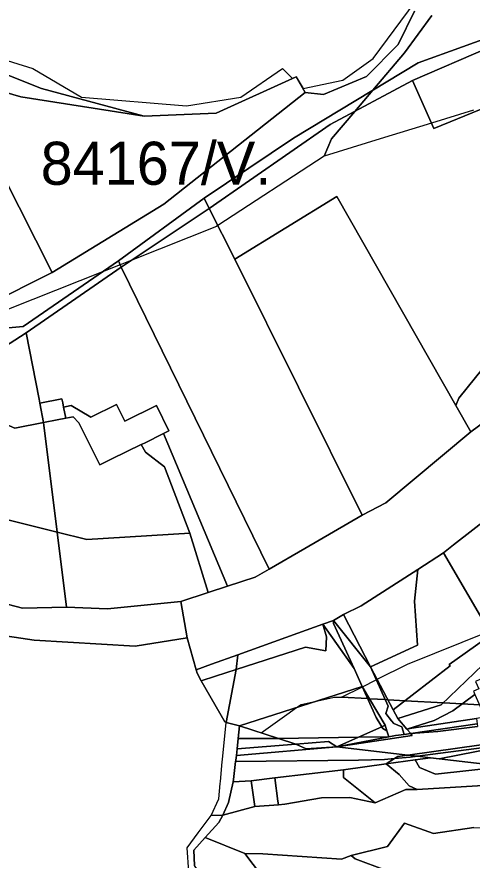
# Model space of a CAD drawing. Extents: x -477304 to -465429, y -1159113 to -1149210.
# Drawn here: x -476165.5 to -476007, y -1154887.3 to -1154593.5 of the extents above; entities that cross this region are included whole.
import ezdxf

# ---------------------------------------------------------------- set-up
doc = ezdxf.new("R2010")
doc.units = 0
for name, color, linetype in [('BPEJ_s', 7, 'Continuous'), ('ostatni_s', 7, 'Continuous'), ('PUPFL_s', 7, 'Continuous'), ('trav_porost_s', 7, 'Continuous'), ('voda_s', 7, 'Continuous'), ('zahrada_s', 7, 'Continuous')]:
    doc.layers.add(name, color=color, linetype=linetype)

msp = doc.modelspace()

# ---------------------------------------------------------------- linework, layer by layer
at = {"layer": 'BPEJ_s'}
msp.add_line((-476052.5, -1154830.5), (-476045.2, -1154826.85), dxfattribs=at)
for points in [[(-476198.5, -1154599.5), (-476160, -1154611.5), (-476143, -1154621.5), (-476106.5, -1154624.5), (-476087.5, -1154621.5), (-476073, -1154611.5), (-476069.54, -1154614.96), (-476068.28, -1154614.39), (-476065.87, -1154618.47), (-476052, -1154615.5), (-476041.5, -1154608), (-476014.5, -1154571.5)], [(-476198.5, -1154599.5), (-476160, -1154611.5), (-476143, -1154621.5), (-476106.5, -1154624.5), (-476087.5, -1154621.5), (-476073, -1154611.5), (-476069.54, -1154614.96), (-476068.28, -1154614.39), (-476065.87, -1154618.47), (-476052, -1154615.5), (-476041.5, -1154608), (-476014.5, -1154571.5)], [(-476021.05, -1154592.95), (-476030.5, -1154606), (-476041.52, -1154618.96), (-476047.84, -1154626.4), (-476056, -1154636), (-476058.5, -1154641.98), (-476095.53, -1154666.19), (-476096, -1154666.5), (-476125.52, -1154678.23), (-476129.54, -1154679.83), (-476135.67, -1154682.27), (-476176.5, -1154698.5)], [(-476006.5, -1154626), (-476021.15, -1154630.51), (-476039, -1154636), (-476058.5, -1154641.98), (-476056, -1154636), (-476047.84, -1154626.4), (-476041.52, -1154618.96), (-476030.5, -1154606), (-476021.05, -1154592.95)], [(-476006.5, -1154626), (-476021.15, -1154630.51), (-476039, -1154636), (-476058.5, -1154641.98), (-476095.53, -1154666.19), (-476096, -1154666.5), (-476125.52, -1154678.23), (-476129.54, -1154679.83), (-476135.67, -1154682.27), (-476176.5, -1154698.5)], [(-476186.81, -1154806.62), (-476159.5, -1154810.64), (-476124.34, -1154812.7), (-476106.2, -1154809.85), (-476103.13, -1154820.94), (-476102.8, -1154822.12), (-476101.3, -1154824.75), (-476093.12, -1154839.08), (-476092.69, -1154839.28), (-476087.95, -1154840.53), (-476080.5, -1154842.93), (-476071.5, -1154836.5), (-476068.12, -1154834.14), (-476066.5, -1154833), (-476060.67, -1154831.73), (-476055, -1154830.5), (-476052.5, -1154830.5)], [(-476004.4, -1154833.17), (-476010.4, -1154832.84), (-476017.01, -1154832.47), (-476030.35, -1154831.73), (-476036.27, -1154831.4), (-476037.28, -1154831.35), (-476039.94, -1154831.2), (-476042.7, -1154831.04), (-476043.32, -1154831.01), (-476052.5, -1154830.5), (-476045.2, -1154826.85), (-476040.36, -1154824.43), (-476040.05, -1154824.28), (-476029.5, -1154819), (-476000.96, -1154807.55)], [(-476045.2, -1154826.85), (-476040.36, -1154824.43), (-476040.05, -1154824.28), (-476029.5, -1154819), (-476000.96, -1154807.55)], [(-476105.62, -1154891.31), (-476106.27, -1154882.94), (-476102.42, -1154877.81), (-476101.31, -1154876.33), (-476097.86, -1154871.73), (-476095.23, -1154865.95), (-476094.73, -1154860.63), (-476094.65, -1154859.83), (-476094, -1154853.04), (-476093.92, -1154852.23), (-476092.69, -1154839.28), (-476087.95, -1154840.53), (-476080.5, -1154842.93), (-476071.5, -1154836.5), (-476068.12, -1154834.14), (-476066.5, -1154833), (-476060.67, -1154831.73), (-476055, -1154830.5), (-476052.5, -1154830.5), (-476043.32, -1154831.01), (-476042.7, -1154831.04), (-476039.94, -1154831.2), (-476037.28, -1154831.35), (-476036.27, -1154831.4), (-476030.35, -1154831.73), (-476017.01, -1154832.47), (-476010.4, -1154832.84), (-476004.4, -1154833.17)]]:
    msp.add_lwpolyline(points, dxfattribs=at)
at = {"layer": 'ostatni_s'}
for points in [[(-475922.61, -1154664.03), (-475947.5, -1154680.92), (-475971.18, -1154711.25), (-476007.43, -1154738.07), (-476012.67, -1154728.85), (-476011.62, -1154726.29), (-475984.03, -1154692.11), (-475951.02, -1154670.96), (-475939.87, -1154667.27), (-475936.86, -1154666.04), (-475923.5, -1154662.02)], [(-476196.33, -1154719.12), (-476196.8, -1154718.13), (-476175.59, -1154708.18), (-476177.93, -1154703.42), (-476176.24, -1154702.49), (-476163.4, -1154701.34), (-476130.13, -1154678.46), (-476129.17, -1154680.68), (-476162.29, -1154703.52), (-476171.9, -1154709.68), (-476172.72, -1154707.98)], [(-476175.38, -1154732.86), (-476180.53, -1154730.65), (-476187.48, -1154730.16), (-476169.24, -1154721.57), (-476168.8, -1154721.36), (-476169.61, -1154719.63), (-476173.24, -1154711.89), (-476171.28, -1154710.96), (-476171.9, -1154709.68), (-476162.29, -1154703.52), (-476157.81, -1154726.68), (-476157.54, -1154728.08), (-476156.24, -1154734.8), (-476166.3, -1154736.74)], [(-476156.24, -1154734.8), (-476157.54, -1154728.08), (-476149.85, -1154726.59), (-476149.59, -1154727.93), (-476149.31, -1154729.41), (-476148.55, -1154733.32), (-476151.52, -1154733.89)], [(-476146.68, -1154728.9), (-476139.75, -1154732.91), (-476130.84, -1154728.5), (-476127.94, -1154734.35), (-476116.97, -1154728.9), (-476112.59, -1154737.73), (-476114.43, -1154738.65), (-476121.15, -1154741.97), (-476122.22, -1154742.49), (-476132.51, -1154747.51), (-476136.67, -1154749.57), (-476143.91, -1154734.97), (-476145.93, -1154732.81), (-476148.55, -1154733.32), (-476149.31, -1154729.41)], [(-476174.99, -1154749.93), (-476175.08, -1154744.99), (-476186.99, -1154745.21), (-476182.21, -1154733.26), (-476175.38, -1154732.86), (-476166.3, -1154736.74), (-476156.24, -1154734.8), (-476151.49, -1154773.02), (-476197.51, -1154761.46), (-476191.03, -1154754.54), (-476189.15, -1154750.19)], [(-476114.43, -1154738.65), (-476092.16, -1154791.84), (-476098.93, -1154794.07), (-476105.33, -1154773.37), (-476114.16, -1154750.21), (-476120.78, -1154745.13), (-476122.22, -1154742.49), (-476121.15, -1154741.97)], [(-475972.08, -1154779.37), (-475973.8, -1154781.4), (-475992.24, -1154798.8), (-476000.81, -1154807.81), (-476016.97, -1154780.18), (-476013.49, -1154777.42), (-475988.63, -1154758.17)], [(-476034.43, -1154834.87), (-476042.39, -1154819.88), (-476026, -1154812.35), (-476027.08, -1154796.99), (-476025.92, -1154785.97), (-476016.97, -1154780.18), (-476000.81, -1154807.81), (-476003.08, -1154810.63), (-476015.02, -1154819.11), (-476014.63, -1154819.62)], [(-476051.8, -1154801.71), (-476042.39, -1154819.88), (-476055.27, -1154803.77)], [(-476065.05, -1154813.06), (-476089.16, -1154820.83), (-476088.63, -1154815.71), (-476067.68, -1154808.25), (-476058.96, -1154805.1), (-476057.66, -1154809.45), (-476057.88, -1154814.34)], [(-476055.29, -1154804.78), (-476048.12, -1154820.49), (-476058.96, -1154805.1), (-476055.27, -1154803.77)], [(-476037.07, -1154836.18), (-476035.01, -1154838.74), (-476034.3, -1154839.62), (-476031.49, -1154840.79), (-476030.7, -1154843.48), (-476033.65, -1154843.9), (-476035.96, -1154844.3), (-476036.75, -1154842.19), (-476037.23, -1154840.25), (-476045.25, -1154826.76), (-476048.12, -1154820.49), (-476055.29, -1154804.78), (-476055.27, -1154803.77), (-476042.39, -1154819.88), (-476036.27, -1154833.6)], [(-476103.13, -1154820.94), (-476097.75, -1154819), (-476088.63, -1154815.71), (-476089.16, -1154820.83), (-476096.32, -1154823.14), (-476101.3, -1154824.75), (-476102.8, -1154822.12)], [(-476093.12, -1154839.08), (-476101.3, -1154824.75), (-476096.32, -1154823.14), (-476089.16, -1154820.83), (-476092.69, -1154839.28)], [(-476036.27, -1154833.6), (-476042.39, -1154819.88), (-476034.43, -1154834.87), (-476032.81, -1154837.91), (-476029.68, -1154841.62), (-476028.39, -1154843.15), (-476030.7, -1154843.48), (-476031.49, -1154840.79), (-476034.3, -1154839.62), (-476035.01, -1154838.74), (-476037.07, -1154836.18)], [(-476045.25, -1154826.76), (-476037.23, -1154840.25), (-476038.46, -1154840.8), (-476038.76, -1154840.3), (-476040.36, -1154837.54)], [(-476028.39, -1154843.15), (-476029.68, -1154841.62), (-476028.03, -1154841.35), (-476005.51, -1154837.95), (-476005.26, -1154839.83)], [(-476074.46, -1154844.88), (-476088.45, -1154844.95), (-476087.95, -1154840.53)], [(-476038.46, -1154840.8), (-476037.23, -1154840.25), (-476036.75, -1154842.19), (-476038.09, -1154841.44)], [(-476028.39, -1154843.15), (-476005.26, -1154839.83), (-476005.14, -1154840.75), (-476018.94, -1154842.48)], [(-476074.46, -1154844.88), (-476046.61, -1154844.46), (-476054.11, -1154847.83), (-476057.03, -1154845.94), (-476068.39, -1154846.84)], [(-476027.82, -1154843.83), (-476054.11, -1154847.83), (-476035.96, -1154844.3), (-476033.65, -1154843.9), (-476030.7, -1154843.48), (-476028.39, -1154843.15)], [(-476054.11, -1154847.83), (-476046.61, -1154844.46), (-476035.96, -1154844.3)], [(-475992.44, -1154845.51), (-475978.91, -1154844.22), (-476018.48, -1154851.95), (-476021.52, -1154851.6), (-476026.01, -1154851.08), (-476003.67, -1154848.1), (-476003.87, -1154847.11)], [(-476088.84, -1154848.45), (-476068.39, -1154846.84), (-476064.84, -1154848.51), (-476054.11, -1154847.83), (-476089.09, -1154850.79)], [(-476088.45, -1154844.95), (-476074.46, -1154844.88), (-476068.39, -1154846.84), (-476088.84, -1154848.45)], [(-476064.84, -1154848.51), (-476068.39, -1154846.84), (-476057.03, -1154845.94), (-476054.11, -1154847.83)], [(-476003.67, -1154848.1), (-476026.01, -1154851.08), (-476029.36, -1154850.69), (-476003.87, -1154847.11)], [(-476033.98, -1154851.89), (-476037.56, -1154852.18), (-476046.52, -1154852.47), (-476089.35, -1154852.88), (-476089.29, -1154852.42), (-476089.09, -1154850.79), (-476054.11, -1154847.83), (-476029.36, -1154850.69), (-476032.86, -1154851.17)], [(-476037.56, -1154852.18), (-476033.98, -1154851.89), (-476036.88, -1154853.74), (-476051.82, -1154855.83), (-476075.68, -1154858.55), (-476083.9, -1154859.63), (-476090.22, -1154860.02), (-476090.12, -1154859.22), (-476089.35, -1154852.88), (-476046.52, -1154852.47)], [(-476026.01, -1154851.08), (-476021.52, -1154851.6), (-476026.78, -1154852.34), (-476036.88, -1154853.74), (-476033.98, -1154851.89), (-476028.62, -1154851.44)], [(-476028.91, -1154861.43), (-476032.42, -1154857.45), (-476036.88, -1154853.74), (-476026.78, -1154852.34), (-476025.31, -1154854.97), (-476019.75, -1154857.31), (-475995.51, -1154854.6), (-475973.65, -1154857.12), (-475966.49, -1154857.95), (-475983.34, -1154859.42), (-476001.3, -1154861.14), (-476026.13, -1154862.63)], [(-476032.86, -1154851.17), (-476029.36, -1154850.69), (-476026.01, -1154851.08), (-476028.62, -1154851.44), (-476033.98, -1154851.89)], [(-476082.72, -1154868.56), (-476082.83, -1154867.76), (-476083.9, -1154859.63), (-476075.68, -1154858.55), (-476074.61, -1154866.68), (-476074.44, -1154868)]]:
    msp.add_lwpolyline(points, close=True, dxfattribs=at)
for points in [[(-476003.87, -1154847.11), (-476029.36, -1154850.69), (-476054.11, -1154847.83), (-476027.82, -1154843.83), (-476028.39, -1154843.15), (-476018.94, -1154842.48), (-476005.14, -1154840.75)], [(-476006.43, -1154875.93), (-476020.4, -1154878.03), (-476030.59, -1154874.38), (-476036.49, -1154882.49), (-476049.12, -1154885.62), (-476052.52, -1154886.99), (-476079.85, -1154885.05), (-476086.18, -1154884.99), (-476099.93, -1154879.38), (-476095.23, -1154874.14), (-476093.86, -1154871.59), (-476082.72, -1154868.56), (-476074.44, -1154868), (-476072.2, -1154867.83), (-476059.4, -1154865.62), (-476049.61, -1154865.49), (-476040.75, -1154867.29), (-476030.13, -1154862.72), (-476026.13, -1154862.63), (-476001.3, -1154861.14)]]:
    msp.add_lwpolyline(points, dxfattribs=at)
at = {"layer": 'PUPFL_s'}
msp.add_lwpolyline([(-476027.06, -1154591.44), (-476032.71, -1154603.05), (-476043.79, -1154614.28), (-476058.75, -1154620.47), (-476065.08, -1154619.8), (-476068.28, -1154614.39), (-476096.08, -1154627.01), (-476121.26, -1154628.12), (-476156.97, -1154618.41), (-476181.02, -1154608.9)], dxfattribs=at)
msp.add_lwpolyline([(-475968.58, -1154873.72), (-475956.34, -1154871.9), (-475947.39, -1154897.37), (-475980.62, -1154902.58), (-475993.17, -1154898.98), (-476014.17, -1154899.41), (-476026.59, -1154894.74), (-476047.73, -1154886.78), (-476049.12, -1154885.62), (-476036.49, -1154882.49), (-476030.59, -1154874.38), (-476020.4, -1154878.03), (-476006.43, -1154875.93), (-475975.16, -1154877.12)], close=True, dxfattribs=at)
at = {"layer": 'trav_porost_s'}
for points in [[(-476291.65, -1154595.44), (-476293.18, -1154577.08), (-476280.73, -1154404.52), (-476260.36, -1154583.68), (-476237.98, -1154597.39), (-476205.4, -1154600.25), (-476181.02, -1154608.9), (-476156.97, -1154618.41), (-476121.26, -1154628.12), (-476164.18, -1154621.32), (-476187.76, -1154614.43), (-476209.8, -1154607.87), (-476232.07, -1154603.98), (-476259.55, -1154603.63), (-476259.31, -1154596.89)], [(-476027.72, -1154615.62), (-476001.35, -1154604.31), (-475979.01, -1154598.12), (-475975.44, -1154600.25), (-475968.59, -1154611.11), (-475971.45, -1154612.42), (-476020.32, -1154632.38)], [(-476288.08, -1154632.32), (-476260.17, -1154621.36), (-476259.55, -1154603.63), (-476232.07, -1154603.98), (-476209.8, -1154607.87), (-476187.76, -1154614.43), (-476153.3, -1154682.48), (-476198.43, -1154705.16), (-476217.72, -1154651.45), (-476276.52, -1154662.47)], [(-476020.32, -1154632.38), (-475971.45, -1154612.42), (-475939.87, -1154667.27), (-475951.02, -1154670.96), (-475984.03, -1154692.11), (-476011.62, -1154726.29), (-476012.67, -1154728.85), (-476054.12, -1154656), (-476089.61, -1154677.88), (-476098.57, -1154660.18), (-476056.4, -1154630.99), (-476027.72, -1154615.62)], [(-476187.76, -1154614.43), (-476164.18, -1154621.32), (-476121.26, -1154628.12), (-476096.08, -1154627.01), (-476068.28, -1154614.39), (-476065.08, -1154619.8), (-476114.35, -1154658.78), (-476153.3, -1154682.48)], [(-476045.28, -1154767.03), (-476089.61, -1154677.88), (-476054.12, -1154656), (-476012.67, -1154728.85), (-476007.43, -1154738.07), (-476037, -1154762.78)], [(-476098.57, -1154660.18), (-476089.61, -1154677.88), (-476045.28, -1154767.03), (-476065.3, -1154778.67), (-476077.71, -1154785.89), (-476129.17, -1154680.68)], [(-476112.59, -1154737.73), (-476116.97, -1154728.9), (-476127.94, -1154734.35), (-476130.84, -1154728.5), (-476139.75, -1154732.91), (-476146.68, -1154728.9), (-476149.31, -1154729.41), (-476149.59, -1154727.93), (-476149.85, -1154726.59), (-476157.54, -1154728.08), (-476157.81, -1154726.68), (-476162.29, -1154703.52), (-476129.17, -1154680.68), (-476077.71, -1154785.89), (-476082.55, -1154788.68), (-476092.16, -1154791.84), (-476114.43, -1154738.65)], [(-476199.92, -1154787.92), (-476202.2, -1154779.49), (-476200.12, -1154764.43), (-476197.51, -1154761.46), (-476151.49, -1154773.02), (-476148.23, -1154799.19), (-476163.64, -1154799.53), (-476197.83, -1154790.6)], [(-476148.23, -1154799.19), (-476151.49, -1154773.02), (-476141.23, -1154775.59), (-476105.33, -1154773.37), (-476098.93, -1154794.07), (-476108.48, -1154797.21), (-476133.97, -1154799.67)], [(-476042.39, -1154819.88), (-476051.8, -1154801.71), (-476045.62, -1154798.73), (-476025.92, -1154785.97), (-476027.08, -1154796.99), (-476026, -1154812.35)], [(-476087.95, -1154840.53), (-476045.25, -1154826.76), (-476040.36, -1154837.54), (-476038.76, -1154840.3), (-476038.46, -1154840.8), (-476046.61, -1154844.46), (-476074.46, -1154844.88)], [(-475922.11, -1154838.33), (-475919.4, -1154841.21), (-475927.39, -1154842.36), (-475935.4, -1154844.62), (-475950.67, -1154847.93), (-475995.51, -1154854.6), (-476018.48, -1154851.95), (-475978.91, -1154844.22), (-475964.26, -1154843.96)], [(-476038.09, -1154841.44), (-476036.75, -1154842.19), (-476035.96, -1154844.3), (-476046.61, -1154844.46), (-476038.46, -1154840.8)], [(-476019.75, -1154857.31), (-476025.31, -1154854.97), (-476026.78, -1154852.34), (-476021.52, -1154851.6), (-476018.48, -1154851.95), (-475995.51, -1154854.6)], [(-476040.75, -1154867.29), (-476049.61, -1154865.49), (-476059.4, -1154865.62), (-476072.2, -1154867.83), (-476074.44, -1154868), (-476074.61, -1154866.68), (-476075.68, -1154858.55), (-476051.82, -1154855.83), (-476051.84, -1154858.54)], [(-476028.91, -1154861.43), (-476026.13, -1154862.63), (-476030.13, -1154862.72), (-476040.75, -1154867.29), (-476051.84, -1154858.54), (-476051.82, -1154855.83), (-476036.88, -1154853.74), (-476032.42, -1154857.45)], [(-476091.83, -1154867.2), (-476090.22, -1154860.02), (-476083.9, -1154859.63), (-476082.83, -1154867.76), (-476082.72, -1154868.56), (-476093.86, -1154871.59)], [(-476091.87, -1154937.78), (-476079.07, -1154940.92), (-476078.07, -1154936.84), (-476086.15, -1154934.86), (-476085.48, -1154931.78), (-476082.64, -1154932.4), (-476081.68, -1154928), (-476084.51, -1154927.38), (-476083.61, -1154923.28), (-476088.07, -1154922.3), (-476091.76, -1154906.33), (-476103.65, -1154889.12), (-476103.87, -1154883.77), (-476099.93, -1154879.38), (-476086.18, -1154884.99), (-476077.11, -1154896.9), (-476068.99, -1154906.54), (-476066.32, -1154918.97), (-476069.11, -1154928.69), (-476076.8, -1154942.35), (-476093.23, -1154948.43)], [(-476065.75, -1154914.12), (-476064.76, -1154937.9), (-476076.8, -1154942.35), (-476069.11, -1154928.69), (-476066.32, -1154918.97), (-476068.99, -1154906.54), (-476077.11, -1154896.9), (-476086.18, -1154884.99), (-476079.85, -1154885.05), (-476052.52, -1154886.99), (-476049.12, -1154885.62), (-476047.73, -1154886.78), (-476026.59, -1154894.74), (-476030.51, -1154895.13), (-476062.72, -1154898.29), (-476058.12, -1154911.67)]]:
    msp.add_lwpolyline(points, close=True, dxfattribs=at)
for points in [[(-475834, -1154588.66), (-475855, -1154614.56), (-475879.24, -1154632.44), (-475903.6, -1154641.58), (-475928.42, -1154645.17), (-475943.01, -1154642.63), (-475949.32, -1154636.48), (-475971.03, -1154597.62), (-475977.86, -1154593.98), (-475994.9, -1154598.32), (-476025.82, -1154609.43), (-476069.17, -1154635.75), (-476100.29, -1154656.65), (-476130.13, -1154678.46), (-476163.4, -1154701.34), (-476176.24, -1154702.49)], [(-476198.43, -1154705.16), (-476153.3, -1154682.48), (-476114.35, -1154658.78), (-476065.08, -1154619.8), (-476058.75, -1154620.47), (-476043.79, -1154614.28), (-476032.71, -1154603.05), (-476027.06, -1154591.44)]]:
    msp.add_lwpolyline(points, dxfattribs=at)
at = {"layer": 'voda_s'}
for points in [[(-475928.42, -1154645.17), (-475928.09, -1154649.52), (-475943.34, -1154646.98), (-475951.86, -1154639.84), (-475968.59, -1154611.11), (-475975.44, -1154600.25), (-475979.01, -1154598.12), (-476001.35, -1154604.31), (-476027.72, -1154615.62), (-476056.4, -1154630.99), (-476098.57, -1154660.18), (-476100.29, -1154656.65), (-476069.17, -1154635.75), (-476025.82, -1154609.43), (-475994.9, -1154598.32), (-475977.86, -1154593.98), (-475971.03, -1154597.62), (-475949.32, -1154636.48), (-475943.01, -1154642.63)], [(-476130.13, -1154678.46), (-476100.29, -1154656.65), (-476098.57, -1154660.18), (-476129.17, -1154680.68)], [(-476048.12, -1154820.49), (-476045.25, -1154826.76), (-476087.95, -1154840.53), (-476092.69, -1154839.28), (-476089.16, -1154820.83), (-476065.05, -1154813.06), (-476057.88, -1154814.34), (-476057.66, -1154809.45), (-476058.96, -1154805.1)], [(-476094, -1154853.04), (-476093.92, -1154852.23), (-476092.69, -1154839.28), (-476087.95, -1154840.53), (-476088.45, -1154844.95), (-476088.84, -1154848.45), (-476089.09, -1154850.79), (-476089.29, -1154852.42), (-476089.35, -1154852.88), (-476090.12, -1154859.22), (-476090.22, -1154860.02), (-476091.83, -1154867.2), (-476093.86, -1154871.59), (-476097.86, -1154871.73), (-476095.23, -1154865.95), (-476094.73, -1154860.63), (-476094.65, -1154859.83)]]:
    msp.add_lwpolyline(points, close=True, dxfattribs=at)
for points in [[(-475988.63, -1154758.17), (-476013.49, -1154777.42), (-476016.97, -1154780.18), (-476025.92, -1154785.97), (-476045.62, -1154798.73), (-476051.8, -1154801.71), (-476055.27, -1154803.77), (-476058.96, -1154805.1), (-476067.68, -1154808.25), (-476088.63, -1154815.71), (-476097.75, -1154819), (-476103.13, -1154820.94), (-476106.2, -1154809.85), (-476108.48, -1154797.21), (-476098.93, -1154794.07), (-476092.16, -1154791.84), (-476082.55, -1154788.68), (-476077.71, -1154785.89), (-476065.3, -1154778.67), (-476045.28, -1154767.03), (-476037, -1154762.78), (-476007.43, -1154738.07), (-475971.18, -1154711.25)], [(-476197.83, -1154790.6), (-476163.64, -1154799.53), (-476148.23, -1154799.19), (-476133.97, -1154799.67), (-476108.48, -1154797.21), (-476106.2, -1154809.85), (-476124.34, -1154812.7), (-476159.5, -1154810.64), (-476186.81, -1154806.62)], [(-476105.62, -1154891.31), (-476106.27, -1154882.94), (-476102.42, -1154877.81), (-476097.86, -1154871.73), (-476093.86, -1154871.59), (-476095.23, -1154874.14), (-476099.93, -1154879.38), (-476103.87, -1154883.77), (-476103.65, -1154889.12)]]:
    msp.add_lwpolyline(points, dxfattribs=at)
at = {"layer": 'zahrada_s'}
for points in [[(-476132.51, -1154747.51), (-476122.22, -1154742.49), (-476120.78, -1154745.13), (-476114.16, -1154750.21), (-476105.33, -1154773.37), (-476141.23, -1154775.59), (-476151.49, -1154773.02), (-476156.24, -1154734.8), (-476151.52, -1154733.89), (-476148.55, -1154733.32), (-476145.93, -1154732.81), (-476143.91, -1154734.97), (-476136.67, -1154749.57)], [(-475992.24, -1154798.8), (-475989.2, -1154802.64), (-475997.45, -1154813.64), (-476017.72, -1154833.15), (-476032.81, -1154837.91), (-476034.43, -1154834.87), (-476014.63, -1154819.62), (-476015.02, -1154819.11), (-476003.08, -1154810.63), (-476000.81, -1154807.81)], [(-476005.85, -1154825.06), (-476004.7, -1154827.61), (-476006.54, -1154828.44), (-476006.02, -1154829.59), (-476013.65, -1154835.25), (-476020.19, -1154838.62), (-476029.68, -1154841.62), (-476032.81, -1154837.91), (-476017.72, -1154833.15), (-475997.45, -1154813.64), (-475989.2, -1154802.64), (-475984.38, -1154808.72), (-475999.23, -1154823.35), (-476002.27, -1154824.73), (-476002.75, -1154823.66)], [(-476006.02, -1154829.59), (-476003.21, -1154835.81), (-475994.04, -1154831.54), (-475997.37, -1154824.17), (-475998.61, -1154824.73), (-475999.23, -1154823.35), (-475984.38, -1154808.72), (-475975.68, -1154819.71), (-475991.37, -1154824.4), (-475991.08, -1154825.36), (-475988.57, -1154833.8), (-475988.12, -1154835.3), (-476005.51, -1154837.95), (-476028.03, -1154841.35), (-476029.68, -1154841.62), (-476020.19, -1154838.62), (-476013.65, -1154835.25)]]:
    msp.add_lwpolyline(points, close=True, dxfattribs=at)

# ---------------------------------------------------------------- texts
at = {"layer": 'BPEJ_s'}
msp.add_text('84167/V.', height=15, dxfattribs=at).set_placement((-476157.25, -1154651.98))

doc.saveas('drawing.dxf')
